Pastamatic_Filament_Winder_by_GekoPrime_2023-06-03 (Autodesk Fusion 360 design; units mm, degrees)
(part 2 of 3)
sketch "Sketch14" plane through (0, 0, -56.4284) normal (0, 0, 1) x axis (1, 0, 0)
  line L1 (-9.2583, 1.6082) -> (-8.3641, 1.4537)
  curve K1 (-11.9856, 0.5875) -> (-9.2583, 1.6082)
  curve K2 (-9.2583, -1.6082) -> (-11.9856, -0.5875)
  line L2 (-8.3641, -1.4537) -> (-9.2583, -1.6082)
  line L3 (-8.4354, -4.1409) -> (-7.6212, -3.7403)
  curve K3 (-10.0419, -6.5697) -> (-8.4354, -4.1409)
  curve K4 (-6.5449, -6.7429) -> (-9.3513, -7.5202)
  line L4 (-5.9123, -6.0924) -> (-6.5449, -6.7429)
  line L5 (-4.3904, -8.3082) -> (-3.9672, -7.5055)
  curve K5 (-4.2625, -11.2175) -> (-4.3904, -8.3082)
  curve K6 (-1.3315, -9.3021) -> (-3.145, -11.5805)
  line L6 (-1.2021, -8.404) -> (-1.3315, -9.3021)
  line L7 (1.3315, -9.3021) -> (1.2021, -8.404)
  curve K7 (3.145, -11.5805) -> (1.3315, -9.3021)
  curve K8 (4.3904, -8.3082) -> (4.2625, -11.2175)
  line L8 (3.9672, -7.5055) -> (4.3904, -8.3082)
  line L9 (6.5449, -6.7429) -> (5.9123, -6.0924)
  curve K9 (9.3513, -7.5202) -> (6.5449, -6.7429)
  curve K10 (8.4354, -4.1409) -> (10.0419, -6.5697)
  line L10 (7.6212, -3.7403) -> (8.4354, -4.1409)
  line L11 (9.2583, -1.6082) -> (8.3641, -1.4537)
  curve K11 (11.9856, -0.5875) -> (9.2583, -1.6082)
  curve K12 (9.2583, 1.6082) -> (11.9856, 0.5875)
  line L12 (8.3641, 1.4537) -> (9.2583, 1.6082)
  line L13 (8.4354, 4.1409) -> (7.6212, 3.7403)
  curve K13 (10.0419, 6.5697) -> (8.4354, 4.1409)
  curve K14 (6.5449, 6.7429) -> (9.3513, 7.5202)
  line L14 (5.9123, 6.0924) -> (6.5449, 6.7429)
  line L15 (4.3904, 8.3082) -> (3.9672, 7.5055)
  curve K15 (4.2625, 11.2175) -> (4.3904, 8.3082)
  curve K16 (1.3315, 9.3021) -> (3.145, 11.5805)
  line L16 (1.2021, 8.404) -> (1.3315, 9.3021)
  line L17 (-1.3315, 9.3021) -> (-1.2021, 8.404)
  curve K17 (-3.145, 11.5805) -> (-1.3315, 9.3021)
  curve K18 (-4.3904, 8.3082) -> (-4.2625, 11.2175)
  line L18 (-3.9672, 7.5055) -> (-4.3904, 8.3082)
  line L19 (-6.5449, 6.7429) -> (-5.9123, 6.0924)
  curve K19 (-9.3513, 7.5202) -> (-6.5449, 6.7429)
  curve K20 (-8.4354, 4.1409) -> (-10.0419, 6.5697)
  line L20 (-7.6212, 3.7403) -> (-8.4354, 4.1409)
  arc A1 centre (-8.1939, 2.4391) radius 1 between (-8.3641, 1.4537) and (-7.2354, 2.1538)
  arc A2 centre (0, 0) radius 12 clockwise from (-11.9856, -0.5875) to (-11.9856, 0.5875)
  arc A3 centre (-8.1939, -2.4391) radius 1 between (-7.2354, -2.1538) and (-8.3641, -1.4537)
  arc A4 centre (0, 0) radius 7.5492 clockwise from (-7.1196, -2.5104) to (-7.2354, -2.1538)
  arc A5 centre (-8.0626, -2.843) radius 1 between (-7.6212, -3.7403) and (-7.1196, -2.5104)
  arc A6 centre (0, 0) radius 12 clockwise from (-9.3513, -7.5202) to (-10.0419, -6.5697)
  arc A7 centre (-5.1953, -6.7895) radius 1 between (-4.5876, -5.9953) and (-5.9123, -6.0924)
  arc A8 centre (0, 0) radius 7.5492 clockwise from (-4.2842, -6.2158) to (-4.5876, -5.9953)
  arc A9 centre (-4.8518, -7.0391) radius 1 between (-3.9672, -7.5055) and (-4.2842, -6.2158)
  arc A10 centre (0, 0) radius 12 clockwise from (-3.145, -11.5805) to (-4.2625, -11.2175)
  arc A11 centre (-0.2123, -8.5466) radius 1 between (-0.1875, -7.5469) and (-1.2021, -8.404)
  arc A12 centre (0, 0) radius 7.5492 clockwise from (0.1875, -7.5469) to (-0.1875, -7.5469)
  arc A13 centre (0.2123, -8.5466) radius 1 between (1.2021, -8.404) and (0.1875, -7.5469)
  arc A14 centre (0, 0) radius 12 clockwise from (4.2625, -11.2175) to (3.145, -11.5805)
  arc A15 centre (4.8518, -7.0391) radius 1 between (4.2842, -6.2158) and (3.9672, -7.5055)
  arc A16 centre (0, 0) radius 7.5492 clockwise from (4.5876, -5.9953) to (4.2842, -6.2158)
  arc A17 centre (5.1953, -6.7895) radius 1 between (5.9123, -6.0924) and (4.5876, -5.9953)
  arc A18 centre (0, 0) radius 12 clockwise from (10.0419, -6.5697) to (9.3513, -7.5202)
  arc A19 centre (8.0626, -2.843) radius 1 between (7.1196, -2.5104) and (7.6212, -3.7403)
  arc A20 centre (0, 0) radius 7.5492 clockwise from (7.2354, -2.1538) to (7.1196, -2.5104)
  arc A21 centre (8.1939, -2.4391) radius 1 between (8.3641, -1.4537) and (7.2354, -2.1538)
  arc A22 centre (0, 0) radius 12 clockwise from (11.9856, 0.5875) to (11.9856, -0.5875)
  arc A23 centre (8.1939, 2.4391) radius 1 between (7.2354, 2.1538) and (8.3641, 1.4537)
  arc A24 centre (0, 0) radius 7.5492 clockwise from (7.1196, 2.5104) to (7.2354, 2.1538)
  arc A25 centre (8.0626, 2.843) radius 1 between (7.6212, 3.7403) and (7.1196, 2.5104)
  arc A26 centre (0, 0) radius 12 clockwise from (9.3513, 7.5202) to (10.0419, 6.5697)
  arc A27 centre (5.1953, 6.7895) radius 1 between (4.5876, 5.9953) and (5.9123, 6.0924)
  arc A28 centre (0, 0) radius 7.5492 clockwise from (4.2842, 6.2158) to (4.5876, 5.9953)
  arc A29 centre (4.8518, 7.0391) radius 1 between (3.9672, 7.5055) and (4.2842, 6.2158)
  arc A30 centre (0, 0) radius 12 clockwise from (3.145, 11.5805) to (4.2625, 11.2175)
  arc A31 centre (0.2123, 8.5466) radius 1 between (0.1875, 7.5469) and (1.2021, 8.404)
  arc A32 centre (0, 0) radius 7.5492 clockwise from (-0.1875, 7.5469) to (0.1875, 7.5469)
  arc A33 centre (-0.2123, 8.5466) radius 1 between (-1.2021, 8.404) and (-0.1875, 7.5469)
  arc A34 centre (0, 0) radius 12 clockwise from (-4.2625, 11.2175) to (-3.145, 11.5805)
  arc A35 centre (-4.8518, 7.0391) radius 1 between (-4.2842, 6.2158) and (-3.9672, 7.5055)
  arc A36 centre (0, 0) radius 7.5492 clockwise from (-4.5876, 5.9953) to (-4.2842, 6.2158)
  arc A37 centre (-5.1953, 6.7895) radius 1 between (-5.9123, 6.0924) and (-4.5876, 5.9953)
  arc A38 centre (0, 0) radius 12 clockwise from (-10.0419, 6.5697) to (-9.3513, 7.5202)
  arc A39 centre (-8.0626, 2.843) radius 1 between (-7.1196, 2.5104) and (-7.6212, 3.7403)
  arc A40 centre (0, 0) radius 7.5492 clockwise from (-7.2354, 2.1538) to (-7.1196, 2.5104)
loft "Loft7" sketch "Sketch13" + "Sketch14"
sketch "Sketch15" plane through (0, 0, -75.0284) normal (0, 0, 1) x axis (1, 0, 0)
  circle C1 centre (0, 0) radius 13
  circle C2 centre (0, 0) radius 13
sketch "Sketch16" plane through (0, 0, -63.4284) normal (0, 0, -1) x axis (-1, 0, 0)
  line L1 (8.4354, 4.1409) -> (7.6212, 3.7403)
  curve K1 (10.0419, 6.5697) -> (8.4354, 4.1409)
  curve K2 (6.5449, 6.7429) -> (9.3513, 7.5202)
  line L2 (5.9123, 6.0924) -> (6.5449, 6.7429)
  line L3 (4.3904, 8.3082) -> (3.9672, 7.5055)
  curve K3 (4.2625, 11.2175) -> (4.3904, 8.3082)
  curve K4 (1.3315, 9.3021) -> (3.145, 11.5805)
  line L4 (1.2021, 8.404) -> (1.3315, 9.3021)
  line L5 (-1.3315, 9.3021) -> (-1.2021, 8.404)
  curve K5 (-3.145, 11.5805) -> (-1.3315, 9.3021)
  curve K6 (-4.3904, 8.3082) -> (-4.2625, 11.2175)
  line L6 (-3.9672, 7.5055) -> (-4.3904, 8.3082)
  line L7 (-6.5449, 6.7429) -> (-5.9123, 6.0924)
  curve K7 (-9.3513, 7.5202) -> (-6.5449, 6.7429)
  curve K8 (-8.4354, 4.1409) -> (-10.0419, 6.5697)
  line L8 (-7.6212, 3.7403) -> (-8.4354, 4.1409)
  line L9 (-9.2583, 1.6082) -> (-8.3641, 1.4537)
  curve K9 (-11.9856, 0.5875) -> (-9.2583, 1.6082)
  curve K10 (-9.2583, -1.6082) -> (-11.9856, -0.5875)
  line L10 (-8.3641, -1.4537) -> (-9.2583, -1.6082)
  line L11 (-8.4354, -4.1409) -> (-7.6212, -3.7403)
  curve K11 (-10.0419, -6.5697) -> (-8.4354, -4.1409)
  curve K12 (-6.5449, -6.7429) -> (-9.3513, -7.5202)
  line L12 (-5.9123, -6.0924) -> (-6.5449, -6.7429)
  line L13 (-4.3904, -8.3082) -> (-3.9672, -7.5055)
  curve K13 (-4.2625, -11.2175) -> (-4.3904, -8.3082)
  curve K14 (-1.3315, -9.3021) -> (-3.145, -11.5805)
  line L14 (-1.2021, -8.404) -> (-1.3315, -9.3021)
  line L15 (1.3315, -9.3021) -> (1.2021, -8.404)
  curve K15 (3.145, -11.5805) -> (1.3315, -9.3021)
  curve K16 (4.3904, -8.3082) -> (4.2625, -11.2175)
  line L16 (3.9672, -7.5055) -> (4.3904, -8.3082)
  line L17 (6.5449, -6.7429) -> (5.9123, -6.0924)
  curve K17 (9.3513, -7.5202) -> (6.5449, -6.7429)
  curve K18 (8.4354, -4.1409) -> (10.0419, -6.5697)
  line L18 (7.6212, -3.7403) -> (8.4354, -4.1409)
  line L19 (9.2583, -1.6082) -> (8.3641, -1.4537)
  curve K19 (11.9856, -0.5875) -> (9.2583, -1.6082)
  curve K20 (9.2583, 1.6082) -> (11.9856, 0.5875)
  line L20 (8.3641, 1.4537) -> (9.2583, 1.6082)
  line L21 (8.4354, 4.1409) -> (7.6212, 3.7403)
  curve K21 (10.0419, 6.5697) -> (8.4354, 4.1409)
  curve K22 (6.5449, 6.7429) -> (9.3513, 7.5202)
  line L22 (5.9123, 6.0924) -> (6.5449, 6.7429)
  line L23 (4.3904, 8.3082) -> (3.9672, 7.5055)
  curve K23 (4.2625, 11.2175) -> (4.3904, 8.3082)
  curve K24 (1.3315, 9.3021) -> (3.145, 11.5805)
  line L24 (1.2021, 8.404) -> (1.3315, 9.3021)
  line L25 (-1.3315, 9.3021) -> (-1.2021, 8.404)
  curve K25 (-3.145, 11.5805) -> (-1.3315, 9.3021)
  curve K26 (-4.3904, 8.3082) -> (-4.2625, 11.2175)
  line L26 (-3.9672, 7.5055) -> (-4.3904, 8.3082)
  line L27 (-6.5449, 6.7429) -> (-5.9123, 6.0924)
  curve K27 (-9.3513, 7.5202) -> (-6.5449, 6.7429)
  curve K28 (-8.4354, 4.1409) -> (-10.0419, 6.5697)
  line L28 (-7.6212, 3.7403) -> (-8.4354, 4.1409)
  line L29 (-9.2583, 1.6082) -> (-8.3641, 1.4537)
  curve K29 (-11.9856, 0.5875) -> (-9.2583, 1.6082)
  curve K30 (-9.2583, -1.6082) -> (-11.9856, -0.5875)
  line L30 (-8.3641, -1.4537) -> (-9.2583, -1.6082)
  line L31 (-8.4354, -4.1409) -> (-7.6212, -3.7403)
  curve K31 (-10.0419, -6.5697) -> (-8.4354, -4.1409)
  curve K32 (-6.5449, -6.7429) -> (-9.3513, -7.5202)
  line L32 (-5.9123, -6.0924) -> (-6.5449, -6.7429)
  line L33 (-4.3904, -8.3082) -> (-3.9672, -7.5055)
  curve K33 (-4.2625, -11.2175) -> (-4.3904, -8.3082)
  curve K34 (-1.3315, -9.3021) -> (-3.145, -11.5805)
  line L34 (-1.2021, -8.404) -> (-1.3315, -9.3021)
  line L35 (1.3315, -9.3021) -> (1.2021, -8.404)
  curve K35 (3.145, -11.5805) -> (1.3315, -9.3021)
  curve K36 (4.3904, -8.3082) -> (4.2625, -11.2175)
  line L36 (3.9672, -7.5055) -> (4.3904, -8.3082)
  line L37 (6.5449, -6.7429) -> (5.9123, -6.0924)
  curve K37 (9.3513, -7.5202) -> (6.5449, -6.7429)
  curve K38 (8.4354, -4.1409) -> (10.0419, -6.5697)
  line L38 (7.6212, -3.7403) -> (8.4354, -4.1409)
  line L39 (9.2583, -1.6082) -> (8.3641, -1.4537)
  curve K39 (11.9856, -0.5875) -> (9.2583, -1.6082)
  curve K40 (9.2583, 1.6082) -> (11.9856, 0.5875)
  line L40 (8.3641, 1.4537) -> (9.2583, 1.6082)
  arc A1 centre (8.1939, 2.4391) radius 1 between (7.2354, 2.1538) and (8.3641, 1.4537)
  arc A2 centre (0, 0) radius 7.5492 clockwise from (7.1196, 2.5104) to (7.2354, 2.1538)
  arc A3 centre (8.0626, 2.843) radius 1 between (7.6212, 3.7403) and (7.1196, 2.5104)
  arc A4 centre (0, 0) radius 12 clockwise from (9.3513, 7.5202) to (10.0419, 6.5697)
  arc A5 centre (5.1953, 6.7895) radius 1 between (4.5876, 5.9953) and (5.9123, 6.0924)
  arc A6 centre (0, 0) radius 7.5492 clockwise from (4.2842, 6.2158) to (4.5876, 5.9953)
  arc A7 centre (4.8518, 7.0391) radius 1 between (3.9672, 7.5055) and (4.2842, 6.2158)
  arc A8 centre (0, 0) radius 12 clockwise from (3.145, 11.5805) to (4.2625, 11.2175)
  arc A9 centre (0.2123, 8.5466) radius 1 between (0.1875, 7.5469) and (1.2021, 8.404)
  arc A10 centre (0, 0) radius 7.5492 clockwise from (-0.1875, 7.5469) to (0.1875, 7.5469)
  arc A11 centre (-0.2123, 8.5466) radius 1 between (-1.2021, 8.404) and (-0.1875, 7.5469)
  arc A12 centre (0, 0) radius 12 clockwise from (-4.2625, 11.2175) to (-3.145, 11.5805)
  arc A13 centre (-4.8518, 7.0391) radius 1 between (-4.2842, 6.2158) and (-3.9672, 7.5055)
  arc A14 centre (0, 0) radius 7.5492 clockwise from (-4.5876, 5.9953) to (-4.2842, 6.2158)
  arc A15 centre (-5.1953, 6.7895) radius 1 between (-5.9123, 6.0924) and (-4.5876, 5.9953)
  arc A16 centre (0, 0) radius 12 clockwise from (-10.0419, 6.5697) to (-9.3513, 7.5202)
  arc A17 centre (-8.0626, 2.843) radius 1 between (-7.1196, 2.5104) and (-7.6212, 3.7403)
  arc A18 centre (0, 0) radius 7.5492 clockwise from (-7.2354, 2.1538) to (-7.1196, 2.5104)
  arc A19 centre (-8.1939, 2.4391) radius 1 between (-8.3641, 1.4537) and (-7.2354, 2.1538)
  arc A20 centre (0, 0) radius 12 clockwise from (-11.9856, -0.5875) to (-11.9856, 0.5875)
  arc A21 centre (-8.1939, -2.4391) radius 1 between (-7.2354, -2.1538) and (-8.3641, -1.4537)
  arc A22 centre (0, 0) radius 7.5492 clockwise from (-7.1196, -2.5104) to (-7.2354, -2.1538)
  arc A23 centre (-8.0626, -2.843) radius 1 between (-7.6212, -3.7403) and (-7.1196, -2.5104)
  arc A24 centre (0, 0) radius 12 clockwise from (-9.3513, -7.5202) to (-10.0419, -6.5697)
  arc A25 centre (-5.1953, -6.7895) radius 1 between (-4.5876, -5.9953) and (-5.9123, -6.0924)
  arc A26 centre (0, 0) radius 7.5492 clockwise from (-4.2842, -6.2158) to (-4.5876, -5.9953)
  arc A27 centre (-4.8518, -7.0391) radius 1 between (-3.9672, -7.5055) and (-4.2842, -6.2158)
  arc A28 centre (0, 0) radius 12 clockwise from (-3.145, -11.5805) to (-4.2625, -11.2175)
  arc A29 centre (-0.2123, -8.5466) radius 1 between (-0.1875, -7.5469) and (-1.2021, -8.404)
  arc A30 centre (0, 0) radius 7.5492 clockwise from (0.1875, -7.5469) to (-0.1875, -7.5469)
  arc A31 centre (0.2123, -8.5466) radius 1 between (1.2021, -8.404) and (0.1875, -7.5469)
  arc A32 centre (0, 0) radius 12 clockwise from (4.2625, -11.2175) to (3.145, -11.5805)
  arc A33 centre (4.8518, -7.0391) radius 1 between (4.2842, -6.2158) and (3.9672, -7.5055)
  arc A34 centre (0, 0) radius 7.5492 clockwise from (4.5876, -5.9953) to (4.2842, -6.2158)
  arc A35 centre (5.1953, -6.7895) radius 1 between (5.9123, -6.0924) and (4.5876, -5.9953)
  arc A36 centre (0, 0) radius 12 clockwise from (10.0419, -6.5697) to (9.3513, -7.5202)
  arc A37 centre (8.0626, -2.843) radius 1 between (7.1196, -2.5104) and (7.6212, -3.7403)
  arc A38 centre (0, 0) radius 7.5492 clockwise from (7.2354, -2.1538) to (7.1196, -2.5104)
  arc A39 centre (8.1939, -2.4391) radius 1 between (8.3641, -1.4537) and (7.2354, -2.1538)
  arc A40 centre (0, 0) radius 12 clockwise from (11.9856, 0.5875) to (11.9856, -0.5875)
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loft "Loft10" sketch "Sketch15" + "Sketch16"
combine "Combine24" bodies "spur_gear_10t_7mm"
sketch "drive" plane through (0, 0, 0) normal (0, 0, 1) x axis (-1, 0, 0)
  line L1 (-1.963, -3.4) -> (1.963, -3.4)
  line L2 (0, 0) -> (1.963, -3.4)
  line L3 (-1.963, -3.4) -> (0, 0)
  line L4 (-1.963, -5.4) -> (1.963, -5.4)
  line L5 (2.963, -5.1321) -> (1.963, -3.4)
  line L6 (-2.963, -5.1321) -> (-1.963, -3.4)
  circle C1 centre (0, 0) radius 15
  circle C2 centre (0, 0) radius 3.4
  arc A1 centre (1.963, -3.4) radius 2 clockwise from (2.963, -5.1321) to (1.963, -5.4)
  arc A2 centre (-1.963, -3.4) radius 2 clockwise from (-1.963, -5.4) to (-2.963, -5.1321)
  arc A3 centre (0, -3.4) radius 0.4156 clockwise from (0.4156, -3.4) to (-0.3636, -3.1986)
  arc A4 centre (0, -3.4) radius 2.4156 clockwise from (1.3547, -5.4) to (-1.3547, -5.4)
  point P1 (0, 0)
  point P3 (0, 0)
  point P6 (0, 0)
  point P4 (1.963, -3.4)
  point P7 (1.963, -3.4)
  point P5 (-1.963, -3.4)
  point P10 (-1.963, -3.4)
  point P13 (1.963, -3.4)
  point P16 (0.4156, -3.4)
  point P14 (0, -3.4)
  point P19 (1.3547, -5.4)
  point P17 (0, -3.4)
  point P18 (-1.3547, -5.4)
  coincident P1 P3
  tangent C2 L1
  coincident P3 P6
  equal L2 L3
  coincident P4 P7
  coincident P5 P10
  coincident P7 P13
  collinear L2 L5
  collinear L3 L6
  tangent A2 L4
  tangent A1 L4
  parallel L1 L4
  coincident L1 P16
  midpoint L1 P14
  coincident L4 P19
  coincident P14 P17
  coincident L4 P18
  horizontal L1
  dimension "d888" diameter C2 = 6.8 (= "drive_span + clearance_loose / 2")
  dimension "d889" angle L2 L3 = 60 (= "( 360 / drive_n_sides ) * 1 deg")
  dimension "d890" distance L1 L4 = 2 (= "wall_thickness")
  dimension "d892" distance A3 A4 = 2 (= "wall_thickness")
  dimension "d893" radius A3 = 0.4156 (= "drive_span / 16")
extrude "Extrude18" sketch "drive" profile of L1 L2 L3 no distance stored
circular_pattern "C-Pattern7" TotalAngle 360
loft "Loft14"
extrude "Extrude19" add of existing geometry blind 2 (= "wall_thickness") taper -45
sketch "Sketch1" plane through (0, 0, 0) normal (0, 0, 1) x axis (1, 0, 0)
  line L1 (0, 0) -> (0, 16.5831)
  line L2 (0, 125) -> (0, -125)
  line L3 (25, 16.5831) -> (-25, 16.5831)
  line L4 (0, 0) -> (-25, 16.5831)
  line L5 (25, 16.5831) -> (0, 0)
  line L6 (62.3842, 108.049) -> (175.0785, 108.049)
  line L7 (183.0785, 128.049) -> (-95, 128.049)
  line L8 (112.9635, 75.7732) -> (62.3842, 108.049)
  line L9 (112.9635, 75.7732) -> (175.0785, 108.049)
  line L10 (-18.3848, 118.5932) -> (13.1117, 87.0967)
  line L11 (183.0785, 128.049) -> (183.0785, 108.049)
  line L12 (1.8396, 51.0572) -> (30.6569, 22.24)
  line L13 (0.277, 151.3971) -> (-7.0711, 144.049)
  line L14 (183.0785, 144.049) -> (-95, 144.049)
  line L15 (183.0785, 128.049) -> (183.0785, 144.049)
  line L16 (0, 144.049) -> (0, 125)
  line L17 (-24.4187, 144.049) -> (-24.4187, 128.049)
  line L18 (-7.0711, 129.9069) -> (-7.0711, 144.049)
  line L19 (-206.2464, 96.6381) -> (-220.8848, 96.6381)
  line L20 (-220.1543, 105.5872) -> (-211.2052, 96.6381)
  line L21 (112.9635, 75.7732) -> (94.777, 86.2732)
  line L22 (131.15, 86.2732) -> (112.9635, 75.7732)
  line L23 (94.777, 86.2732) -> (131.15, 86.2732)
  line L24 (175, 65.7732) -> (67, 65.7732)
  line L25 (128.2235, 66.3204) -> (179.5938, 101.4452)
  line L26 (57.0973, 102.045) -> (97.4011, 66.5555)
  line L27 (151.8964, 82.5069) -> (143.5323, 94.7396)
  line L28 (74.8858, 86.3813) -> (83.5193, 96.1861)
  line L29 (128.2235, 66.3204) -> (119.6113, 76.6889)
  line L30 (97.4011, 66.5555) -> (106.0346, 76.3603)
  line L31 (4.1421, 126.978) -> (7.0711, 129.9069)
  line L32 (-4.1421, 126.978) -> (4.1421, 126.978)
  line L33 (-7.0711, 129.9069) -> (-4.1421, 126.978)
  line L34 (7.0711, 129.9069) -> (7.0711, 144.049)
  line L35 (-7.0711, 129.9069) -> (7.0711, 129.9069)
  line L36 (40, -14) -> (-52.1436, -14)
  line L37 (-21.6788, -11.5706) -> (-32.3575, 13.4419)
  line L38 (32.3575, 13.4419) -> (21.6788, -11.5706)
  line L39 (-14, 0) -> (-14, -10)
  line L40 (14, -10) -> (14, 0)
  line L41 (167.0785, 128.049) -> (167.0785, 108.049)
  line L42 (-180.3192, 97.2293) -> (-165.6808, 97.2293)
  line L43 (18.7877, 34.1091) -> (6.8934, 22.2148)
  line L44 (-24.002, 39.3233) -> (-6.8934, 22.2148)
  line L45 (24.4187, 144.049) -> (24.4187, 128.049)
  line L46 (-24.4187, 124.978) -> (-24.4187, 128.049)
  line L47 (24.4187, 124.978) -> (-24.4187, 124.978)
  line L48 (24.4187, 128.049) -> (24.4187, 124.978)
  line L49 (120.9635, 110.8518) -> (120.9635, 75.7732)
  line L50 (104.9635, 110.21) -> (104.9635, 75.7732)
  line L51 (-5.8383, -13.9607) -> (-9.8995, -9.8995)
  line L52 (6.9829, -14.0477) -> (-5.8383, -13.9607)
  line L53 (11.2177, -8.3764) -> (6.9829, -14.0477)
  circle C1 centre (0, 0) radius 125
  circle C2 centre (-25, 16.5831) radius 20
  circle C3 centre (25, 16.5831) radius 20
  circle C4 centre (62.3842, 108.049) radius 10
  circle C5 centre (112.9635, 75.7732) radius 50
  circle C6 centre (0, 0) radius 10
  circle C7 centre (112.9635, 75.7732) radius 10
  circle C8 centre (175.0785, 108.049) radius 20
  circle C9 centre (19.6153, 82.1488) radius 20
  circle C10 centre (-7.04, 52.3244) radius 20
  arc A1 centre (118.7313, -33.2588) radius 152.1279 clockwise from (-25, 16.5831) to (175.0785, 108.049)
  circle C11 centre (25, 16.5831) radius 8
  circle C12 centre (-25, 16.5831) radius 8
  circle C13 centre (-7.04, 52.3244) radius 8
  circle C14 centre (19.6153, 82.1488) radius 8
  circle C15 centre (175.0785, 108.049) radius 8
  arc A2 centre (118.7313, -33.2588) radius 144.1279 clockwise from (-17.4416, 13.9621) to (172.1153, 100.618)
  arc A3 centre (118.7313, -33.2588) radius 160.1279 clockwise from (-32.5585, 19.2039) to (178.0416, 115.48)
  arc A4 centre (0, 136.978) radius 10 clockwise from (7.0711, 144.049) to (-7.0711, 144.049)
  arc A5 centre (175.0785, 108.049) radius 8 clockwise from (178.0416, 115.48) to (172.1153, 100.618)
  arc A6 centre (-25, 16.5831) radius 8 clockwise from (-17.4416, 13.9621) to (-32.5585, 19.2039)
  circle C16 centre (-25, 16.5831) radius 24
  circle C17 centre (-7.04, 52.3244) radius 24
  circle C18 centre (19.6153, 82.1488) radius 24
  circle C19 centre (62.3842, 108.049) radius 14
  circle C20 centre (175.0785, 108.049) radius 24
  circle C21 centre (25, 16.5831) radius 24
  circle C22 centre (-25, 16.5831) radius 4.15
  circle C23 centre (25, 16.5831) radius 4.15
  circle C24 centre (-7.04, 52.3244) radius 4.15
  circle C25 centre (19.6153, 82.1488) radius 4.15
  circle C26 centre (62.3842, 108.049) radius 4.15
  circle C27 centre (175.0785, 108.049) radius 4.15
  circle C28 centre (-213.5656, 93.4087) radius 4
  circle C29 centre (-213.5656, 93.4087) radius 8
  circle C30 centre (131.15, 86.2732) radius 4.15
  circle C31 centre (94.777, 86.2732) radius 4.15
  circle C32 centre (131.15, 86.2732) radius 11
  circle C33 centre (94.777, 86.2732) radius 11
  arc A7 centre (112.9635, 75.7732) radius 12 clockwise from (102.2684, 70.3312) to (123.6586, 70.3312)
  arc A8 centre (126.4535, 68.9091) radius 3.1359 clockwise from (128.2235, 66.3204) to (123.6586, 70.3312)
  arc A9 centre (99.4735, 68.9091) radius 3.1359 clockwise from (102.2684, 70.3312) to (97.4011, 66.5555)
  circle C34 centre (131.15, 86.2732) radius 15
  circle C35 centre (94.777, 86.2732) radius 15
  circle C36 centre (0, 0) radius 100
  circle C37 centre (112.9635, 75.7732) radius 54
  circle C38 centre (0, 16.5831) radius 1
  circle C39 centre (0, 0) radius 14
  circle C40 centre (62.3842, 108.049) radius 30
  circle C41 centre (62.3842, 108.049) radius 34
  arc A10 centre (-18, -10) radius 4 clockwise from (-14, -10) to (-21.6788, -11.5706)
  arc A11 centre (18, -10) radius 4 clockwise from (21.6788, -11.5706) to (14, -10)
  arc A12 centre (0, 136.978) radius 26 clockwise from (24.4187, 128.049) to (-24.4187, 128.049)
  circle C42 centre (62.3842, 108.049) radius 8
  circle C43 centre (-173, 94) radius 4
  circle C44 centre (-173, 94) radius 8
  circle C45 centre (17.5, 11.6082) radius 4.15
  circle C46 centre (17.5, 11.6082) radius 11
  circle C47 centre (17.5, 11.6082) radius 15
  circle C48 centre (-17.5, 11.6082) radius 4.15
  circle C49 centre (-17.5, 11.6082) radius 11
  circle C50 centre (-17.5, 11.6082) radius 15
  circle C51 centre (62.3842, 108.049) radius 36
  circle C52 centre (112.9635, 75.7732) radius 4.15
  arc A13 centre (112.9635, 75.7732) radius 8 clockwise from (120.9635, 75.7732) to (104.9635, 75.7732)
  arc A14 centre (0, 1.8708) radius 25.5619 clockwise from (21.3392, -12.2022) to (-21.3392, -12.2022)
  point P1 (0, 0)
  point P2 (0, 0)
  point P9 (0, 0)
  point P10 (0, -125)
  point P11 (0, 125)
  point P7 (0, 0)
  point P15 (-7.04, 52.3244)
  point P4 (25, 16.5831)
  point P20 (25, 16.5831)
  point P8 (0, 16.5831)
  point P18 (-25, 16.5831)
  point P19 (-25, 16.5831)
  point P3 (-25, 16.5831)
  point P21 (-25, 16.5831)
  point P14 (19.6153, 82.1488)
  point P22 (-25, 16.5831)
  point P23 (0, 0)
  point P24 (0, 0)
  point P25 (25, 16.5831)
  point P13 (175.0785, 108.049)
  point P26 (175.0785, 108.049)
  point P5 (62.3842, 108.049)
  point P27 (62.3842, 108.049)
  point P30 (62.3842, 108.049)
  point P6 (112.9635, 75.7732)
  point P31 (112.9635, 75.7732)
  point P32 (175.0785, 108.049)
  point P12 (112.9635, 75.7732)
  point P33 (112.9635, 75.7732)
  point P34 (25, 16.5831)
  point P38 (175.0785, 108.049)
  point P41 (-17.4416, 13.9621)
  point P17 (175.0785, 108.049)
  point P40 (172.1153, 100.618)
  point P42 (-32.5585, 19.2039)
  point P45 (-32.5585, 19.2039)
  point P39 (118.7313, -33.2588)
  point P43 (118.7313, -33.2588)
  point P16 (118.7313, -33.2588)
  point P47 (-24.4187, 128.049)
  point P48 (183.0785, 108.049)
  point P49 (183.0785, 128.049)
  point P53 (175.0785, 108.049)
  point P56 (-32.5585, 19.2039)
  point P35 (-25, 16.5831)
  point P55 (-25, 16.5831)
  point P69 (30.6569, 22.24)
  point P70 (1.8396, 51.0572)
  point P44 (178.0416, 115.48)
  point P54 (178.0416, 115.48)
  point P72 (-32.3575, 13.4419)
  point P73 (32.3575, 13.4419)
  point P29 (183.0785, 128.049)
  point P52 (7.0711, 144.049)
  point P76 (-7.0711, 144.049)
  point P51 (-7.0711, 144.049)
  point P77 (0, 144.049)
  point P50 (0, 136.978)
  point P78 (-24.4187, 144.049)
  point P79 (0, 25.5242)
  point P80 (-7.0711, 129.9069)
  point P83 (-220.8848, 96.6381)
  point P86 (-206.2464, 96.6381)
  point P84 (-211.2052, 96.6381)
  point P88 (94.777, 86.2732)
  point P91 (94.777, 86.2732)
  point P92 (112.9635, 75.7732)
  point P93 (112.9635, 75.7732)
  point P89 (131.15, 86.2732)
  point P94 (131.15, 86.2732)
  point P96 (112.9635, 75.7732)
  point P105 (179.5938, 101.4452)
  point P109 (143.5323, 94.7396)
  point P110 (151.8964, 82.5069)
  point P111 (83.5193, 96.1861)
  point P112 (74.8858, 86.3813)
  point P113 (119.6113, 76.6889)
  point P114 (106.0346, 76.3603)
  point P115 (7.0711, 129.9069)
  point P118 (0, 0)
  point P95 (94.777, 86.2732)
  point P90 (94.777, 86.2732)
  point P120 (0, 16.5831)
  point P132 (-14, 0)
  point P133 (14, 0)
  point P134 (167.0785, 108.049)
  point P135 (167.0785, 128.049)
  point P137 (-24.4187, 128.049)
  point P136 (0, 136.978)
  point P138 (24.4187, 128.049)
  point P46 (13.1117, 87.0967)
  point P139 (-18.3848, 118.5932)
  point P106 (57.0973, 102.045)
  point P67 (62.3842, 108.049)
  point P123 (62.3842, 108.049)
  point P60 (62.3842, 108.049)
  point P122 (62.3842, 108.049)
  point P143 (-165.6808, 97.2293)
  point P144 (-180.3192, 97.2293)
  point P147 (17.5, 11.6082)
  point P148 (-17.5, 11.6082)
  point P152 (6.8934, 22.2148)
  point P153 (18.7877, 34.1091)
  point P154 (-6.8934, 22.2148)
  point P155 (-24.002, 39.3233)
  point P156 (24.4187, 144.049)
  point P157 (0, 100)
  point P161 (112.9635, 75.7732)
  point P164 (120.9635, 110.8518)
  point P165 (104.9635, 110.21)
  point P166 (-9.8995, -9.8995)
  point P169 (11.2177, -8.3764)
  point P171 (-21.3392, -12.2022)
  point P170 (0, 1.8708)
  point P172 (21.3392, -12.2022)
  point P119 (112.9635, 75.7732)
  coincident P1 P2
  concentric C1 C6
  tangent C2 C6
  coincident P1 P9
  vertical L1
  coincident C1 P10
  coincident C1 P11
  vertical L2
  midpoint P7 L2
  concentric C5 C7
  tangent C9 C10
  tangent C2 C10
  tangent C3 C6
  coincident P15 A1
  coincident P4 P20
  midpoint P8 L3
  coincident P18 P19
  horizontal L3
  tangent C5 C8
  coincident P3 P21
  coincident P14 A1
  coincident P3 P19
  coincident P21 P22
  coincident P1 P23
  coincident P2 P24
  coincident P4 P25
  coincident P13 P26
  coincident P5 P27
  coincident P5 A1
  horizontal L6
  horizontal L7
  equal C2 C10
  equal C2 C9
  equal C2 C8
  coincident P5 P30
  coincident P6 P31
  coincident P13 P32
  coincident P12 P33
  coincident P20 P34
  concentric C2 C12
  concentric C10 C13
  concentric C9 C14
  coincident P26 P38
  equal C11 C12
  equal C12 C13
  equal C12 C15
  tangent C12 A2
  coincident C12 P41
  coincident P17 P38
  coincident C15 P40
  coincident P42 P45
  coincident P39 P43
  coincident C12 P42
  coincident P16 P43
  tangent C12 A3
  coincident L7 P47
  coincident C15 P48
  coincident L7 P49
  perpendicular L7 L11
  tangent C15 L11
  coincident P13 P53
  coincident P42 P56
  coincident P35 P55
  concentric A6 C16
  concentric C13 C17
  concentric C14 C18
  concentric C15 C20
  equal C16 C17
  equal C16 C18
  equal C16 C20
  concentric C3 C21
  equal C16 C21
  concentric C16 C22
  concentric C3 C23
  concentric C13 C24
  concentric C14 C25
  concentric C4 C26
  concentric A5 C27
  equal C22 C23
  equal C22 C24
  equal C22 C25
  equal C22 C27
  coincident C11 P69
  coincident A2 P70
  tangent C11 L12
  tangent A4 L13
  coincident P44 P54
  tangent A2 A5
  coincident C12 P72
  coincident C11 P73
  perpendicular L11 L14
  perpendicular L14 L15
  coincident P29 P49
  coincident P52 L14
  coincident L14 P76
  coincident P51 P76
  coincident L14 P77
  perpendicular L14 L16
  coincident P50 L16
  coincident L14 P78
  perpendicular L14 L17
  coincident L2 P79
  coincident A4 P80
  concentric C28 C29
  horizontal L19
  coincident C29 P83
  coincident C29 P86
  coincident P84 L19
  coincident C28 P84
  concentric C30 C32
  equal C22 C31
  equal C22 C30
  equal C32 C33
  tangent C7 C32
  tangent C7 C33
  coincident P88 P91
  coincident P6 P92
  coincident P12 P93
  coincident P89 P94
  horizontal L23
  coincident P6 P96
  tangent A7 A8
  horizontal L24
  tangent C7 L24
  tangent A8 L24
  tangent A9 L24
  tangent A7 A9
  coincident A5 P105
  tangent A8 L25
  tangent A9 L26
  tangent C15 L25
  concentric C30 C34
  concentric C33 C35
  equal C34 C35
  coincident C34 P109
  coincident L25 P110
  perpendicular L25 L27
  coincident C35 P111
  coincident L26 P112
  perpendicular L26 L28
  tangent C35 L28
  tangent C34 L27
  equal A8 A9
  coincident C34 P113
  tangent C34 L29
  coincident C35 P114
  tangent C35 L30
  coincident A4 P115
  horizontal L32
  equal L31 L33
  perpendicular L14 L18
  perpendicular L14 L34
  tangent A4 L32
  tangent A4 L31
  coincident P1 P118
  parallel L28 L30
  concentric C7 C37
  coincident P88 P95
  coincident P88 P90
  coincident P8 P120
  tangent C21 C38
  concentric C1 C39
  concentric C4 C40
  tangent C4 C5
  tangent C9 C40
  horizontal L36
  coincident C39 P132
  coincident C39 P133
  tangent A10 L39
  tangent C39 L39
  tangent C39 L40
  tangent A11 L40
  tangent A11 L36
  tangent A10 L36
  tangent C11 L38
  tangent C12 L37
  tangent A10 L37
  tangent A11 L38
  perpendicular L36 L39
  perpendicular L36 L40
  tangent C39 L36
  tangent C17 C21
  coincident C15 P134
  coincident L7 P135
  perpendicular L7 L41
  tangent C15 L41
  coincident L7 P137
  coincident P50 P136
  coincident L7 P138
  coincident A3 P46
  tangent L10 A12
  coincident A12 P139
  coincident P47 P137
  concentric C4 C42
  equal C15 C42
  coincident P106 C42
  tangent L26 C42
  coincident P67 P123
  coincident P60 P122
  equal C13 C14
  concentric C43 C44
  coincident C44 P143
  coincident C44 P144
  horizontal L42
  equal C28 C43
  equal C29 C44
  equal L19 L42
  concentric C45 C46
  concentric C46 C47
  equal C34 C47
  equal C32 C46
  equal C30 C45
  tangent C6 C46
  coincident L5 P147
  coincident L4 P148
  concentric C48 C49
  concentric C48 C50
  equal C45 C48
  equal C46 C49
  equal C47 C50
  tangent C6 C49
  concentric C4 C51
  tangent L14 C51
  equal A10 A11
  coincident C47 P152
  coincident L12 P153
  perpendicular L12 L43
  coincident C50 P154
  coincident A3 P155
  tangent C47 L43
  tangent C50 L44
  perpendicular L43 L44
  coincident L14 P156
  perpendicular L14 L45
  coincident C36 P157
  coincident L2 P157
  perpendicular L7 L46
  perpendicular L47 L48
  perpendicular L46 L47
  concentric C5 C52
  equal C30 C52
  coincident P12 P161
  equal C15 A13
  coincident A2 P164
  coincident A2 P165
  tangent A13 L49
  tangent A13 L50
  vertical L50
  vertical L49
  coincident C39 P166
  coincident C39 P169
  tangent C39 L51
  tangent C39 L53
  tangent C39 L52
  coincident A10 P171
  coincident L2 P170
  coincident A11 P172
  tangent A10 A14
  tangent A11 A14
  dimension "d899_1" diameter C1 = 250 (= "spool_od_max")
  dimension "d900_1" diameter C6 = 20 (= "spur_gear_diameter_small")
  dimension "d1336" diameter C5 = 100 (= "spur_gear_diameter_large")
  dimension "d1345" diameter C2 = 40 (= "spur_gear_diameter_medium")
  dimension "d1347" angle L8 L9 = 120
  dimension "d1348" diameter C12 = 16 (= "bearing_id * 2")
  dimension "d1352" radius A4 = 10 (= "crossbar_od / 2")
  dimension "d1357" diameter C22 = 8.3 (= "bearing_id + clearance_loose")
  dimension "d1358" angle L2 L12 = 45
  dimension "d1361" angle L7 L13 = 45
  dimension "d1379" distance L7 L14 = 16 (= "bearing_id * 2")
  dimension "d1394" diameter C28 = 8 (= "bearing_id")
  dimension "d1395" distance C28 C29 = 4 (= "2 * wall_thickness")
  dimension "d1396" angle L19 L20 = 45
  dimension "d1434" diameter C7 = 20 (= "leadscrew_od")
  dimension "d1445" diameter C32 = 22 (= "bearing_od")
  dimension "d1446" angle L21 L22 = 120
  dimension "d1447" distance C7 A7 = 2 (= "wall_thickness")
  dimension "d1448" distance C32 C34 = 4 (= "spur_gear_clearance")
  dimension "d1449" diameter C36 = 200 (= "spool_od_bambu")
  dimension "d1451" angle L4 L5 = 112.885
  dimension "d1452" distance C5 C37 = 4 (= "spur_gear_clearance")
  dimension "d1453" distance C2 C16 = 4 (= "spur_gear_clearance")
  dimension "d1454" diameter C38 = 2 (= "wall_thickness")
  dimension "d1473" distance C6 C39 = 4 (= "spur_gear_clearance")
  dimension "d1519" distance A4 A12 = 16 (= "bearing_id * 2")
  dimension "d1520" angle L7 L10 = 45
  dimension "d1549" distance L14 P119 = 68.2759
  dimension "d1592" diameter C26 = 8.3 (= "bearing_id + clearance_loose")
  dimension "d1593" diameter C4 = 20 (= "spur_gear_diameter_small")
  dimension "d1594" distance C4 C19 = 4 (= "spur_gear_clearance")
  dimension "d1635" distance C40 C41 = 4 (= "spur_gear_clearance")
  dimension "d1636" diameter C40 = 60
  dimension "d1637" distance C41 C51 = 2 (= "wall_thickness")
  dimension "d1638" radius A10 = 4 (= "bearing_id / 2")
  dimension "d1792" distance L32 L47 = 2 (= "wall_thickness")
  dimension "d1960" angle L2 L51 = 45
position "Position6"
fillet "Fillet3" radius 2 (= "wall_thickness")
sketch "Sketch38" plane through (0, 0, -60.828) normal (0, 0, 1) x axis (-1, 0, 0)
  line L1 (18.0564, 41.8174) -> (0, 0)
  line L2 (45.3505, -4.2503) -> (0, 0)
  line L3 (39.1876, 23.2177) -> (0, 0)
  line L4 (6.3211, 9.594) -> (19.8751, 40.9843)
  line L5 (45.4933, -2.255) -> (11.451, 0.9356)
  curve K1 (-48.1376, -4.0404) -> (-49.3996, -4.5314)
  curve K2 (-48.1376, -4.0404) -> (-47.4527, -3.027)
  curve K3 (-47.458, -2.9442) -> (-48.2644, -2.0247)
  curve K4 (-49.578, -1.6957) -> (-48.2644, -2.0247)
  curve K5 (-48.2644, 2.0247) -> (-49.578, 1.6957)
  curve K6 (-48.2644, 2.0247) -> (-47.458, 2.9442)
  curve K7 (-47.4527, 3.027) -> (-48.1376, 4.0404)
  curve K8 (-49.3996, 4.5314) -> (-48.1376, 4.0404)
  curve K9 (-47.6301, 8.0579) -> (-48.9745, 7.8961)
  curve K10 (-47.6301, 8.0579) -> (-46.7147, 8.8691)
  curve K11 (-46.6992, 8.9506) -> (-47.2516, 10.0418)
  curve K12 (-48.4421, 10.6871) -> (-47.2516, 10.0418)
  curve K13 (-46.2446, 13.9639) -> (-47.5987, 13.972)
  curve K14 (-46.2446, 13.9639) -> (-45.2348, 14.654)
  curve K15 (-45.2091, 14.733) -> (-45.6205, 15.8848)
  curve K16 (-46.7207, 16.6742) -> (-45.6205, 15.8848)
  curve K17 (-44.1298, 19.6498) -> (-45.4722, 19.8275)
  curve K18 (-44.1298, 19.6498) -> (-43.0415, 20.2079)
  curve K19 (-43.0061, 20.283) -> (-43.2698, 21.4773)
  curve K20 (-44.2624, 22.3984) -> (-43.2698, 21.4773)
  curve K21 (-41.319, 25.0258) -> (-42.6286, 25.3703)
  curve K22 (-41.319, 25.0258) -> (-40.1693, 25.4431)
  curve K23 (-40.1249, 25.5132) -> (-40.2368, 26.7311)
  curve K24 (-41.1061, 27.7693) -> (-40.2368, 26.7311)
  curve K25 (-37.8567, 30.0071) -> (-39.1127, 30.5131)
  curve K26 (-37.8567, 30.0071) -> (-36.6637, 30.277)
  curve K27 (-36.6108, 30.341) -> (-36.5692, 31.5633)
  curve K28 (-37.3016, 32.7023) -> (-36.5692, 31.5633)
  curve K29 (-33.7973, 34.5152) -> (-34.98, 35.1746)
  curve K30 (-33.7973, 34.5152) -> (-32.5799, 34.6335)
  curve K31 (-32.5194, 34.6903) -> (-32.3249, 35.8978)
  curve K32 (-32.9088, 37.1196) -> (-32.3249, 35.8978)
  curve K33 (-29.2049, 38.479) -> (-30.2956, 39.2814)
  curve K34 (-29.2049, 38.479) -> (-27.9823, 38.4437)
  curve K35 (-27.9151, 38.4925) -> (-27.5709, 39.6661)
  curve K36 (-27.9969, 40.9515) -> (-27.5709, 39.6661)
  curve K37 (-24.1519, 41.8359) -> (-25.1335, 42.7687)
  curve K38 (-24.1519, 41.8359) -> (-22.9433, 41.6477)
  curve K39 (-22.8706, 41.6877) -> (-22.382, 42.8089)
  curve K40 (-22.6436, 44.1375) -> (-22.382, 42.8089)
  curve K41 (-18.718, 44.533) -> (-19.575, 45.5815)
  curve K42 (-18.718, 44.533) -> (-17.5426, 44.1948)
  curve K43 (-17.4654, 44.2254) -> (-16.8401, 45.2765)
  curve K44 (-16.9332, 46.6275) -> (-16.8401, 45.2765)
  curve K45 (-12.9889, 46.5279) -> (-13.7077, 47.6755)
  curve K46 (-12.9889, 46.5279) -> (-11.8652, 46.045)
  curve K47 (-11.7848, 46.0657) -> (-11.0327, 47.0301)
  curve K48 (-10.9557, 48.3821) -> (-11.0327, 47.0301)
  curve K49 (-7.055, 47.7889) -> (-7.6243, 49.0176)
  curve K50 (-7.055, 47.7889) -> (-6.0007, 47.169)
  curve K51 (-5.9183, 47.1794) -> (-5.0512, 48.0421)
  curve K52 (-4.8054, 49.3737) -> (-5.0512, 48.0421)
  curve K53 (-1.0099, 48.2963) -> (-1.4207, 49.5866)
  curve K54 (-1.0099, 48.2963) -> (-0.0415, 47.5492)
  curve K55 (0.0415, 47.5492) -> (1.0099, 48.2963)
  curve K56 (1.4207, 49.5866) -> (1.0099, 48.2963)
  curve K57 (5.0512, 48.0421) -> (4.8054, 49.3737)
  curve K58 (5.0512, 48.0421) -> (5.9183, 47.1794)
  curve K59 (6.0007, 47.169) -> (7.055, 47.7889)
  curve K60 (7.6243, 49.0176) -> (7.055, 47.7889)
  curve K61 (11.0327, 47.0301) -> (10.9557, 48.3821)
  curve K62 (11.0327, 47.0301) -> (11.7848, 46.0657)
  curve K63 (11.8652, 46.045) -> (12.9889, 46.5279)
  curve K64 (13.7077, 47.6755) -> (12.9889, 46.5279)
  curve K65 (16.8401, 45.2765) -> (16.9332, 46.6275)
  curve K66 (16.8401, 45.2765) -> (17.4654, 44.2254)
  curve K67 (17.5426, 44.1948) -> (18.718, 44.533)
  curve K68 (19.575, 45.5815) -> (18.718, 44.533)
  curve K69 (22.382, 42.8089) -> (22.6436, 44.1375)
  curve K70 (22.382, 42.8089) -> (22.8706, 41.6877)
  curve K71 (22.9433, 41.6477) -> (24.1519, 41.8359)
  curve K72 (25.1335, 42.7687) -> (24.1519, 41.8359)
  curve K73 (27.5709, 39.6661) -> (27.9969, 40.9515)
  curve K74 (27.5709, 39.6661) -> (27.9151, 38.4925)
  curve K75 (27.9823, 38.4437) -> (29.2049, 38.479)
  curve K76 (30.2956, 39.2814) -> (29.2049, 38.479)
  curve K77 (32.3249, 35.8978) -> (32.9088, 37.1196)
  curve K78 (32.3249, 35.8978) -> (32.5194, 34.6903)
  curve K79 (32.5799, 34.6335) -> (33.7973, 34.5152)
  curve K80 (34.98, 35.1746) -> (33.7973, 34.5152)
  curve K81 (36.5692, 31.5633) -> (37.3016, 32.7023)
  curve K82 (36.5692, 31.5633) -> (36.6108, 30.341)
  curve K83 (36.6637, 30.277) -> (37.8567, 30.0071)
  curve K84 (39.1127, 30.5131) -> (37.8567, 30.0071)
  curve K85 (40.2368, 26.7311) -> (41.1061, 27.7693)
  curve K86 (40.2368, 26.7311) -> (40.1249, 25.5132)
  curve K87 (40.1693, 25.4431) -> (41.319, 25.0258)
  curve K88 (42.6286, 25.3703) -> (41.319, 25.0258)
  curve K89 (43.2698, 21.4773) -> (44.2624, 22.3984)
  curve K90 (43.2698, 21.4773) -> (43.0061, 20.283)
  curve K91 (43.0415, 20.2079) -> (44.1298, 19.6498)
  curve K92 (45.4722, 19.8275) -> (44.1298, 19.6498)
  curve K93 (45.6205, 15.8848) -> (46.7207, 16.6742)
  curve K94 (45.6205, 15.8848) -> (45.2091, 14.733)
  curve K95 (45.2348, 14.654) -> (46.2446, 13.9639)
  curve K96 (47.5987, 13.972) -> (46.2446, 13.9639)
  curve K97 (47.2516, 10.0418) -> (48.4421, 10.6871)
  curve K98 (47.2516, 10.0418) -> (46.6992, 8.9506)
  curve K99 (46.7147, 8.8691) -> (47.6301, 8.0579)
  curve K100 (48.9745, 7.8961) -> (47.6301, 8.0579)
  curve K101 (48.1376, 4.0404) -> (49.3996, 4.5314)
  curve K102 (48.1376, 4.0404) -> (47.4527, 3.027)
  curve K103 (47.458, 2.9442) -> (48.2644, 2.0247)
  curve K104 (49.578, 1.6957) -> (48.2644, 2.0247)
  curve K105 (48.2644, -2.0247) -> (49.578, -1.6957)
  curve K106 (48.2644, -2.0247) -> (47.458, -2.9442)
  curve K107 (47.4527, -3.027) -> (48.1376, -4.0404)
  curve K108 (49.3996, -4.5314) -> (48.1376, -4.0404)
  curve K109 (47.6301, -8.0579) -> (48.9745, -7.8961)
  curve K110 (47.6301, -8.0579) -> (46.7147, -8.8691)
  curve K111 (46.6992, -8.9506) -> (47.2516, -10.0418)
  curve K112 (48.4421, -10.6871) -> (47.2516, -10.0418)
  curve K113 (46.2446, -13.9639) -> (47.5987, -13.972)
  curve K114 (46.2446, -13.9639) -> (45.2348, -14.654)
  curve K115 (45.2091, -14.733) -> (45.6205, -15.8848)
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  point P3 (0, 0)
  point P4 (0, 0)
  point P8 (0, 0)
  point P10 (0, 0)
  point P1 (0, 0)
  point P6 (0, 0)
  point P19 (0, 0)
  point P17 (18.0564, 41.8174)
  point P20 (18.0564, 41.8174)
  point P21 (25.7643, 15.2648)
  point P371 (1.8882, 1.1187)
  point P22 (0, 0)
  point P77 (0, 0)
  coincident P3 P4
  coincident P3 P8
  coincident P3 P10
  coincident P1 P6
  coincident P1 P10
  coincident P3 P19
  coincident P17 P20
  parallel L1 L4
  parallel L2 L5
  coincident L3 P21
  coincident L3 P371
  dimension "d1258" distance = 2 (= "wall_thickness")
  dimension "d1259" angle L1 L2 = 72 (= "( 360 / 5 ) * 1 deg")
  dimension "d1260" distance L1 L4 = 2 (= "wall_thickness")
  dimension "d1261" radius = 2 (= "fillet_radius")
  dimension "d1263" diameter = 31.2047
  dimension "d1442" distance P22 P77 = 0 (= "1.709E-08 mm")
  dimension "d1957" diameter = 8.6 (= "bearing_id + 2 * clearance_loose")
extrude "Extrude19" cut sketch "Sketch38" no distance stored
circular_pattern "C-Pattern1" TotalAngle 360
extrude "Extrude28" cut sketch "Sketch38" no distance stored
chamfer "Chamfer6" distance 2 (= "wall_thickness")
sketch "Sketch10" plane through (0, 0, 0) normal (0, 0, 1) x axis (1, 0, 0)
  circle C1 centre (-7.04, 52.3244) radius 4.15
  circle C2 centre (-25, 16.5831) radius 4.15
  circle C3 centre (25, 16.5831) radius 4.15
  circle C4 centre (-17.5, 11.6082) radius 4.15
  circle C5 centre (17.5, 11.6082) radius 4.15
  circle C6 centre (19.6153, 82.1488) radius 4.15
  circle C7 centre (62.3842, 108.049) radius 4.15
  circle C8 centre (94.777, 86.2732) radius 4.15
  circle C9 centre (131.15, 86.2732) radius 4.15
  circle C10 centre (175.0785, 108.049) radius 4.15
  circle C11 centre (-25, 16.5831) radius 5.15
  circle C12 centre (-17.5, 11.6082) radius 5.15
  circle C13 centre (-7.04, 52.3244) radius 5.15
  circle C14 centre (25, 16.5831) radius 5.15
  circle C15 centre (17.5, 11.6082) radius 5.15
  circle C16 centre (19.6153, 82.1488) radius 5.15
  circle C17 centre (62.3842, 108.049) radius 5.15
  circle C18 centre (94.777, 86.2732) radius 5.15
  circle C19 centre (131.15, 86.2732) radius 5.15
  circle C20 centre (175.0785, 108.049) radius 5.15
  concentric C2 C11
  concentric C4 C12
  concentric C1 C13
  concentric C3 C14
  concentric C5 C15
  concentric C6 C16
  concentric C7 C17
  concentric C8 C18
  concentric C9 C19
  concentric C10 C20
  equal C19 C20
  equal C18 C20
  equal C17 C20
  equal C16 C20
  equal C13 C20
  equal C11 C20
  equal C12 C20
  equal C15 C20
  equal C14 C20
  dimension "d1673" distance C10 C20 = 1 (= "washer_radial_thichness")
extrude "Extrude35" new body sketch "Sketch1" profile of L7 C11 C12 A2 A3 L10 L11 A4 A5 A6 C16 C17 C18 C19 C20 C21 C22 C23 C24 C25 C26 C27 L12 L14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 distance 23.2 (= "2 * stack_unit")
extrude "Extrude36" cut sketch "Sketch1" profile of L7 C11 C12 A2 A3 L10 A6 C16 C17 C18 C19 C21 C22 C23 C24 C25 C26 L12 L26 C35 L28 C37 C39 C41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 no distance stored
extrude "Extrude51" cut sketch "Sketch1" profile of L7 A2 A3 L11 A5 C19 C20 C26 C27 L15 C30 C31 A7 A8 A9 L25 L26 C34 C35 L27 L28 L29 L30 C37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 blind 7.3 (= "bearing_z + clearance_loose") from offset 2 (= "wall_thickness")
extrude "Extrude52" sketch "Sketch1" profile of A2 A3 C19 C26 L26 C37 to an object
extrude "Extrude93" sketch "Sketch1" profile of A2 A7 C34 C35 L29 L30 C52 A13 L49 L50 to an object
extrude "Extrude37" cut sketch "Sketch1" profile of L7 A4 C22 C23 C24 C25 C26 C27 L14 L31 L32 L33 L35 C52 no distance stored
extrude "Extrude62" sketch "Sketch10" profile of C1 C2 C3 C4 C5 C6 C7 C11 C12 C13 C14 C15 C16 C17 blind 0.3 (= "washer_z") taper -45 (= "washer_taper")
extrude "Extrude63" sketch "Sketch10" profile of C1 C2 C3 C4 C5 C6 C11 C12 C13 C14 C15 C16 no distance stored taper -45 (= "washer_taper")
extrude "Extrude64" sketch "Sketch10" profile of C10 C20 blind 0.3 (= "washer_z") taper -45 (= "washer_taper")
extrude "Extrude65" sketch "Sketch10" profile of C7 C10 C17 C20 no distance stored taper -45 (= "washer_taper")
extrude "Extrude53" cut sketch "Sketch1" profile of C16 C21 C39 to an object taper 45
fillet "Fillet10" radius 16 (= "2 * bearing_id")
extrude "Extrude38" new body sketch "Sketch1" profile of L7 C11 C12 A2 A3 L10 L11 A4 A5 A6 C16 C17 C18 C19 C20 C21 C22 C23 C24 C25 C26 C27 L12 L14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 distance 11.6 (= "stack_unit") from offset 200 (= "spool_od_bambu") bodies "passive_target_cradle"
extrude "Extrude39" cut sketch "Sketch1" profile of C11 C12 A2 A3 A6 C17 C22 C23 L12 C30 C31 A7 L25 L26 C34 C35 L27 L28 L29 L30 C39 C41 L37 L38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 distance 7.3 (= "bearing_z + clearance_loose") from offset 200 (= "spool_od_bambu")
extrude "Extrude40" cut sketch "Sketch1" profile of L7 C11 C12 A2 A4 A6 L14 C30 C31 L31 L32 L33 L35 C45 C48 no distance stored
extrude "Extrude66" sketch "Sketch10" profile of C2 C3 C4 C5 C8 C9 C11 C12 C14 C15 C18 C19 blind 0.3 (= "washer_z") taper -45 (= "washer_taper")
extrude "Extrude67" sketch "Sketch10" profile of C2 C3 C4 C5 C8 C9 C11 C12 C14 C15 C18 C19 no distance stored taper -45 (= "washer_taper")
fillet "Fillet11" radius 16 (= "2 * bearing_id")
extrude "Extrude41" new body sketch "Sketch1" profile of L7 C11 C12 A2 A3 L10 L11 A4 A5 A6 C16 C17 C18 C19 C20 C21 C22 C23 C24 C25 C26 C27 L12 L14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 distance 11.6 (= "stack_unit") bodies "source_cradle"
extrude "Extrude42" cut sketch "Sketch1" profile of C11 C12 A2 A3 A6 C17 C22 C23 L12 C39 L37 L38 L39 L40 C45 C47 C48 C50 L43 L44 distance 7.3 (= "bearing_z + clearance_loose")
extrude "Extrude43" cut sketch "Sketch1" profile of L7 C11 C12 A2 A4 A6 L14 L31 L32 L33 L35 C45 C48 no distance stored
extrude "Extrude68" sketch "Sketch10" profile of C2 C3 C4 C5 C11 C12 C14 C15 no distance stored taper -45 (= "washer_taper")
extrude "Extrude69" sketch "Sketch10" profile of C2 C3 C4 C5 C11 C12 C14 C15 blind 0.3 (= "washer_z") taper -45 (= "washer_taper")
fillet "Fillet18" radius 16 (= "2 * bearing_id")
extrude "Extrude44" new body sketch "Sketch1" profile of L7 A4 L14 L35 distance 200 (= "leadscrew_length") bodies "cradle_crossbar"
chamfer "Chamfer14" distance 2 (= "wall_thickness")
extrude "Extrude54" new body sketch "Sketch1" profile of C28 C29 L19 C43 C44 L42 along normal blind 2 (= "wall_thickness") bodies "pin_long", "pin_short"
extrude "Extrude55" sketch "Sketch1" profile of C28 L19 C43 L42 blind 8 (= "bearing_id")
extrude "Extrude56" sketch "Sketch1" profile of C28 C29 L19 C43 C44 L42 blind 2 (= "wall_thickness")
extrude "Extrude57" add sketch "Sketch1" profile of C28 L19 against normal blind 31.2 (magnitude of "-stack_unit * 2 - bearing_id")
extrude "Extrude58" add sketch "Sketch1" profile of C43 L42 no distance stored
fillet "Fillet20" radius 4 (= "bearing_id / 2")
fillet "Fillet19" radius 0.6667 (= "wall_thickness / 3")
sketch "Sketch8" plane through (0, 0, 0) normal (0, 1, 0) x axis (1, 0, 0)
  line L1 (161.6576, -117.4748) -> (172.3688, -117.4748)
  line L2 (161.6576, -105.8748) -> (172.3688, -105.8748)
  line L3 (161.6576, -117.4748) -> (161.6576, -105.8748)
  line L4 (161.6576, -111.6748) -> (172.3688, -111.6748)
  line L5 (172.3688, -117.4748) -> (172.3688, -113.6748)
  line L6 (172.3688, -105.8748) -> (172.3688, -109.6748)
  line L7 (172.3688, -113.6748) -> (172.3688, -109.6748)
  line L8 (172.3688, -115.4748) -> (174.0858, -115.4748)
  line L9 (174.0858, -107.8748) -> (174.0858, -115.4748)
  arc A1 centre (167.4576, -111.6748) radius 3.8 clockwise from (169.9132, -114.5748) to (169.9132, -108.7748)
  arc A2 centre (172.3688, -117.4748) radius 3.8 clockwise from (169.9132, -114.5748) to (172.3688, -113.6748)
  arc A3 centre (172.3688, -105.8748) radius 3.8 clockwise from (172.3688, -109.6748) to (169.9132, -108.7748)
  circle C1 centre (167.4576, -111.6748) radius 5.8
  arc A4 centre (167.4576, -111.6748) radius 3.5 clockwise from (169.7194, -114.3459) to (169.7194, -109.0038)
  arc A5 centre (172.3688, -105.8748) radius 4.1 clockwise from (172.3688, -109.9748) to (169.7194, -109.0038)
  arc A6 centre (172.3688, -117.4748) radius 4.1 clockwise from (169.7194, -114.3459) to (172.3688, -113.3748)
  arc A7 centre (172.3688, -115.3937) radius 1.7188 clockwise from (172.3688, -113.6748) to (174.0858, -115.4748)
  arc A8 centre (172.3688, -107.956) radius 1.7188 clockwise from (174.0858, -107.8748) to (172.3688, -109.6748)
  arc A9 centre (172.3688, -107.956) radius 2.0188 clockwise from (174.0858, -109.018) to (172.3688, -109.9748)
  arc A10 centre (172.3688, -115.3937) radius 2.0188 clockwise from (172.3688, -113.3748) to (174.0858, -114.3316)
  point P7 (169.9132, -108.7748)
  point P12 (169.9132, -108.7748)
  point P15 (161.6576, -111.6748)
  point P6 (167.4576, -111.6748)
  point P14 (172.3688, -111.6748)
  point P9 (172.3688, -117.4748)
  point P13 (172.3688, -109.6748)
  point P17 (172.3688, -109.6748)
  point P18 (167.4576, -111.6748)
  point P11 (172.3688, -105.8748)
  point P21 (172.3688, -105.8748)
  point P23 (172.3688, -117.4748)
  point P24 (172.3688, -113.3748)
  point P22 (172.3688, -109.9748)
  point P27 (172.3688, -107.956)
  point P29 (172.3688, -115.4748)
  point P30 (172.3688, -107.956)
  point P32 (172.3688, -115.3937)
  point P31 (174.0858, -109.018)
  point P33 (174.0858, -114.3316)
  point P25 (172.3688, -115.3937)
  point P2 (172.3688, -117.4748)
  point P3 (172.3688, -105.8748)
  point P10 (172.3688, -113.6748)
  perpendicular L1 L3
  tangent A1 A2
  tangent A1 A3
  coincident P7 P12
  midpoint L3 P15
  coincident P6 L4
  concentric A1 C1
  tangent L1 C1
  perpendicular L1 L5
  perpendicular L2 L6
  midpoint P14 L7
  collinear L5 L7
  collinear L6 L7
  horizontal L1
  perpendicular L3 L4
  equal A2 A3
  coincident P9 L5
  coincident P13 P17
  equal A1 A2
  tangent L3 C1
  coincident P6 P18
  coincident P11 P21
  coincident P9 P23
  coincident L7 P24
  coincident L7 P22
  tangent A4 A6
  tangent A4 A5
  tangent A2 A7
  coincident L6 P27
  equal A7 A8
  coincident L5 P29
  perpendicular L5 L8
  vertical L9
  coincident L6 P30
  coincident L5 P32
  coincident L9 P31
  coincident L9 P33
  coincident P27 P30
  coincident P25 P32
  dimension "d1653" distance P2 P3 = 11.6 (= "stack_unit")
  dimension "d1654" distance A1 C1 = 2 (= "wall_thickness")
  dimension "d1656" distance P10 P17 = 4 (= "wall_thickness * 2")
  dimension "d1657" distance A1 A4 = 0.3 (= "clearance_loose")
  dimension "d1670" distance P23 L8 = 2 (= "wall_thickness")
extrude "Extrude59" sketch "Sketch8" profile of A1 A2 A3 L7 A4 A5 A6 A7 A8 L9 A9 A10 blind 14 (= "2 * bearing_z")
